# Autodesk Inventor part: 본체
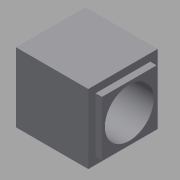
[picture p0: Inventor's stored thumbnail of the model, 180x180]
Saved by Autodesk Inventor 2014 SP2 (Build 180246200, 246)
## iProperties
Created: 2026-01
Part Number: 본체
Material: Generic
Document SubType Name: Modeling
Designer: Administrator
Density: 1 g/cm^3
Appearance: Default
Author: Administrator
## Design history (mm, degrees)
sketch "스케치1"
  geometry: L1 (-74, -71)-(74, -71); L2 (74, -71)-(74, 71); L3 (74, 71)-(-74, 71); L4 (-74, 71)-(-74, -71); L5 (-74, -71)-(74, 71); L6 (74, -71)-(-74, 71); 1 further point
  constraints: 12 end point, 2 midpoint, 2 parallel, 1 horizontal, 1 perpendicular
  dimensions: "d0" = 148 distance of L2.end L3.end; "d1" = 142 distance of L3.end L1.start
extrude "돌출1" new body sketch "스케치1" distance "d2" = 142; taper "d3" = 0 deg
sketch "스케치2"
  geometry: L1 (0, 142)-(-142, 142) reference; L2 (0, 142)-(-142, 142); L3 (-127, 15)-(-15, 15); L4 (-15, 15)-(-15, 127); L5 (-15, 127)-(-127, 127); L6 (-127, 127)-(-127, 15); L7 (-127, 15)-(-71, 71); L8 (-15, 15)-(-71, 71); 1 further point
  constraints: 16 end point, 3 equal length, 1 horizontal, 1 perpendicular
  dimensions: "d5" = 112 distance of L5.end L4.end; "d6" = 112 distance of L4.end L3.end
extrude "돌출2" join sketch "스케치2" distance "d7" = 13; taper "d8" = 0 deg
sketch "스케치4"
  geometry: C1 r 50 at (-71, 71); 1 further point
  constraints: 1 centre point
  dimensions: "d11" = 100 diameter of C1
extrude "돌출3" cut sketch "스케치4" distance "d12" = 200; taper "d13" = 0 deg
node "솔리드1"
other parameters: "d4" = 71
